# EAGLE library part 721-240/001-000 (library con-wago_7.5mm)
Serie 721, Stiftleiste (für Leiterplatten) Einlötstift gerade 1 x 1 mm / Series 721, Male header (for PCBs) Straight solder pin 1 x 1 mm Polzahl / Pole No.: 10 Rastermaß / Pitch: 7.5 mm Bemessungsspannung / Rated Voltage: 630 V Nennstrom / Nominal Current: 12 A Lötstiftlänge: / Solder Pin Length: 5 mm Farbe / Color: lichtgrau / light gray Stand: 01.01.2012. Die jeweils aktuellen Daten zu diesem Artikel finden Sie in unserem Produktkatalog, den Sie unter www.wago.com einsehen können. As of: 01/01/2012. Please find the newest data for this article in our product catalogue, which can be viewed under www.wago.com.
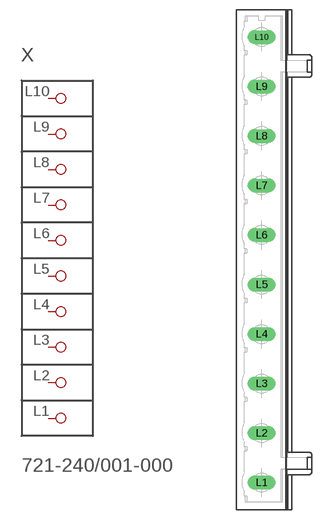
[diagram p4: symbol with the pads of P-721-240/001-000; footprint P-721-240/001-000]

Designator prefix X

## 721-240/001-000  [P-721-240/001-000]
L1  P1
L2  P2
L3  P3
L4  P4
L5  P5
L6  P6
L7  P7
L8  P8
L9  P9
L10  P10

## Footprint P-721-240/001-000 (pad centres in mm)
drill 1.4 long: L1 -1.9,-33.75; L2 -1.9,-26.25; L3 -1.9,-18.75; L4 -1.9,-11.25; L5 -1.9,-3.75; L6 -1.9,3.75; L7 -1.9,11.25; L8 -1.9,18.75; L9 -1.9,26.25; L10 -1.9,33.75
